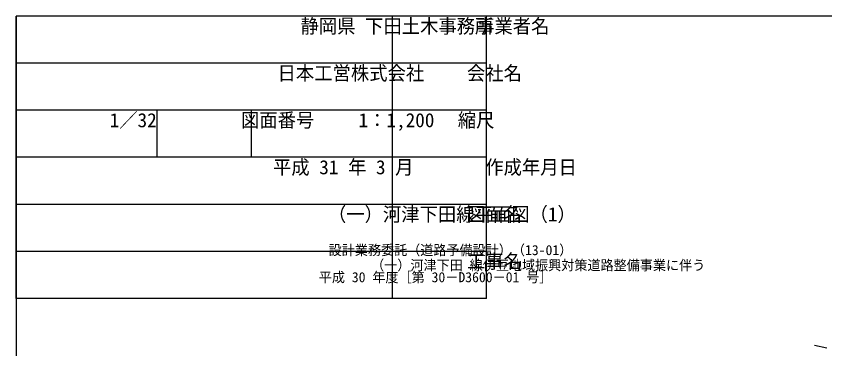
# Model space of a CAD drawing. Extents: x 42655 to 43811, y -141820 to -141156.
# Drawn here: x 42724.6 to 42964.5, y -141254.3 to -141155.6 of the extents above; entities that cross this region are included whole.
import ezdxf

# ---------------------------------------------------------------- set-up
doc = ezdxf.new("R2010")
doc.units = 0
for name, color, linetype in [('D-TTL', 7, 'Continuous'), ('D-TTL-FRAM', 7, 'Continuous'), ('D-TTL-LINE', 7, 'Continuous'), ('D-TTL-TXT', 7, 'Continuous'), ('ZE_HICN', 7, 'Continuous')]:
    doc.layers.add(name, color=color, linetype=linetype)

msp = doc.modelspace()

# ---------------------------------------------------------------- linework, layer by layer
at = {"layer": 'D-TTL'}
msp.add_lwpolyline([(42724.63, -141820.4), (43685.83, -141820.39), (43685.82, -141155.59), (42724.62, -141155.6), (42724.63, -141820.4)], dxfattribs=at)
at = {"layer": 'D-TTL-FRAM'}
for p, q in [((42864.16, -141155.6), (42724.62, -141155.6)), ((42724.62, -141239.32), (42724.62, -141155.6)), ((42864.16, -141239.32), (42864.16, -141155.6)), ((42864.16, -141239.32), (42724.62, -141239.32))]:
    msp.add_line(p, q, dxfattribs=at)
at = {"layer": 'D-TTL-LINE'}
for p, q in [((42836.25, -141239.32), (42836.25, -141155.6)), ((42864.16, -141169.55), (42724.62, -141169.55)), ((42864.16, -141183.5), (42724.62, -141183.51)), ((42766.48, -141197.46), (42766.48, -141183.51)), ((42794.39, -141197.46), (42794.39, -141183.51)), ((42864.16, -141197.46), (42724.62, -141197.46)), ((42864.16, -141211.41), (42724.62, -141211.41)), ((42864.16, -141225.36), (42724.62, -141225.37))]:
    msp.add_line(p, q, dxfattribs=at)
at = {"layer": 'ZE_HICN'}
msp.add_lwpolyline([(42961.43, -141253.2), (42965.07, -141253.93)], dxfattribs=at)

# ---------------------------------------------------------------- texts
at = {"layer": 'D-TTL-TXT'}
for s, height, p in [('静岡県 下田土木事務所', 4.1823, (42808.97, -141160.63)), ('事業者名', 4.182, (42861.07, -141160.62)), ('日本工営株式会社', 4.182, (42802.17, -141174.58)), ('会社名', 4.182, (42858.36, -141174.58)), ('1／32', 4.182, (42752.35, -141188.53)), ('図面番号', 4.182, (42791.31, -141188.53)), ('1：1,200', 4.182, (42826.19, -141188.53)), ('縮尺', 4.182, (42855.64, -141188.53)), ('平成 31 年 3 月', 4.1823, (42800.82, -141202.49)), ('作成年月日', 4.182, (42863.79, -141202.49)), ('（一）河津下田線平面図（1）', 4.1823, (42817.12, -141216.44)), ('図面名', 4.182, (42858.36, -141216.44)), ('設計業務委託（道路予備設計）（13-01） ', 2.9873, (42817.32, -141226.47)), ('工事名', 4.182, (42858.36, -141230.39)), ('（一）河津下田 線伊豆地域振興対策道路整備事業に伴う', 2.9873, (42829.93, -141230.95)), ('平成 30 年度［第 30－D3600－01 号］', 2.9873, (42814.4, -141234.51))]:
    msp.add_text(s, height=height, dxfattribs=at).set_placement(p)

doc.saveas('drawing.dxf')
